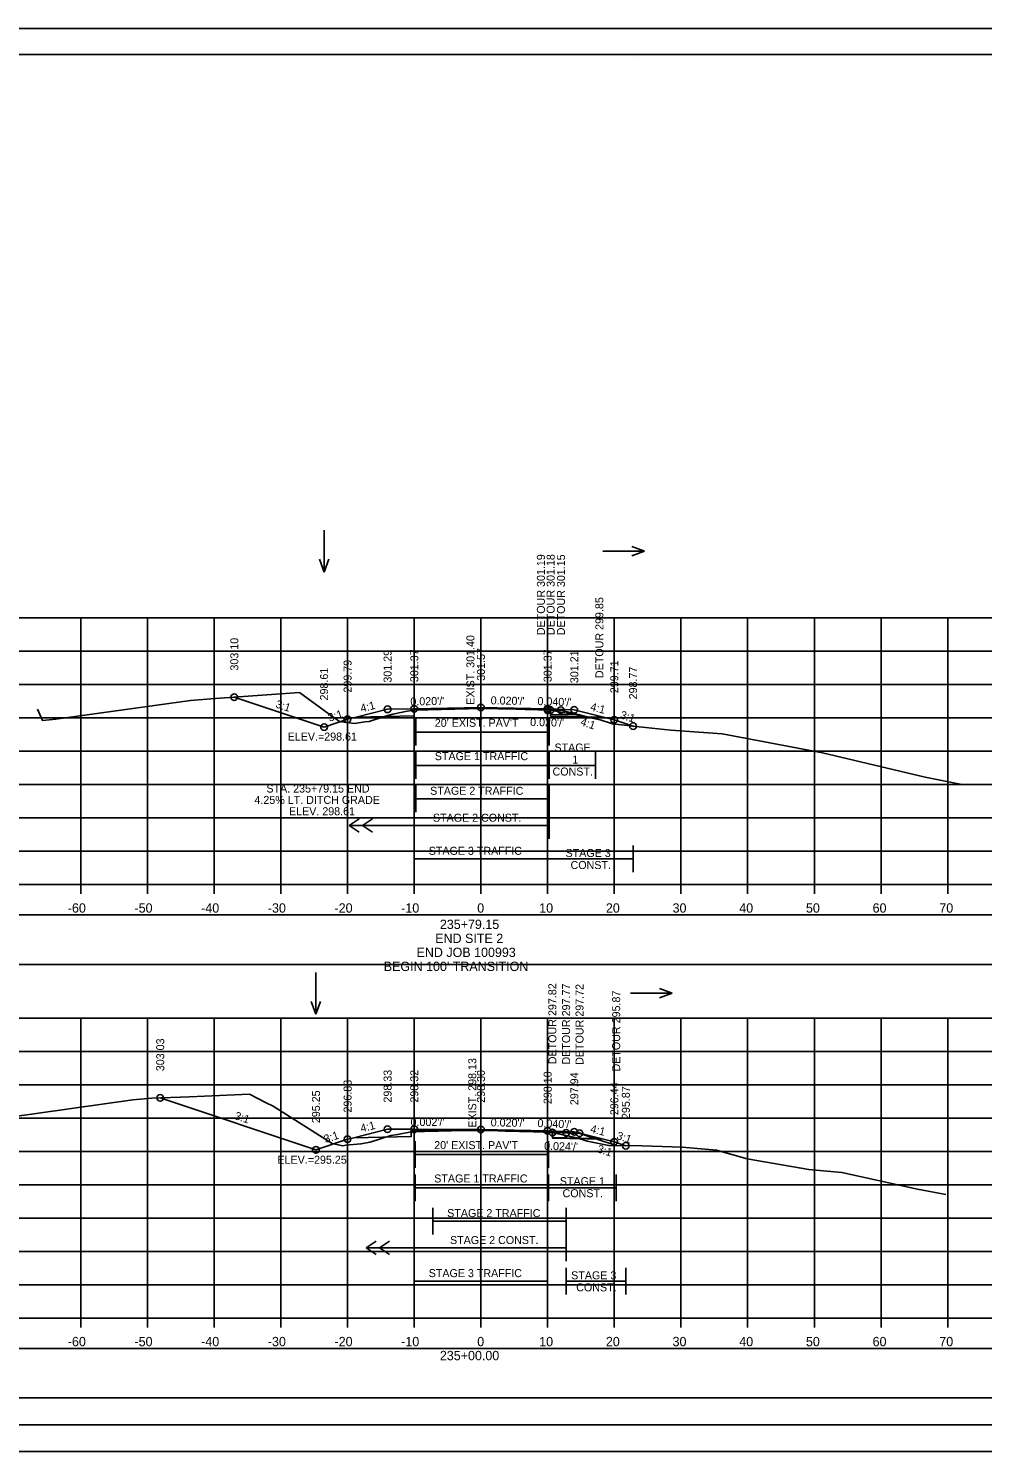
# Model space of a CAD drawing. Extents: x 4667 to 1632277, y -2100 to 724501.
# Drawn here: x 5709.3 to 5852.4, y 1449.6 to 1663 of the extents above; entities that cross this region are included whole.
import ezdxf

# ---------------------------------------------------------------- set-up
doc = ezdxf.new("R2010")
doc.units = 0
for name, color, linetype in [('R_Alt Surface', 7, 'Continuous'), ('R_Axis', 7, 'Continuous'), ('R_Axis Annot', 7, 'Continuous'), ('R_Border', 7, 'Continuous'), ('R_Detour', 7, 'Continuous'), ('R_Detour Annot', 7, 'Continuous'), ('R_Exist Surface', 7, 'Continuous'), ('R_Fin Surface', 7, 'Continuous'), ('R_Fin Surface Annot', 7, 'Continuous'), ('R_Grid', 7, 'Continuous'), ('R_No Plot', 7, 'Continuous'), ('R_Proposed CofA', 7, 'Continuous'), ('R_Temp Easement', 7, 'Continuous'), ('R_Water Annot', 7, 'Continuous'), ('T_Notes', 7, 'Continuous')]:
    doc.layers.add(name, color=color, linetype=linetype)

msp = doc.modelspace()

# ---------------------------------------------------------------- linework, layer by layer
at = {"layer": 'R_Alt Surface'}
for points in [[(5758.47, 1559.74), (5767.18, 1559.91), (5767.18, 1560.83), (5777.18, 1561.03), (5787.63, 1560.82), (5787.63, 1559.9), (5795.55, 1559.74)], [(5758.13, 1496.69), (5766.72, 1496.87), (5766.72, 1497.78), (5777.18, 1497.76), (5787.89, 1497.55), (5787.89, 1496.63), (5795.55, 1496.48)]]:
    msp.add_lwpolyline(points, dxfattribs=at)
at = {"layer": 'R_Axis'}
for p, q in [((5667.18, 1534.63), (5947.18, 1534.63)), ((5717.18, 1533.23), (5717.18, 1534.63)), ((5727.18, 1533.23), (5727.18, 1534.63)), ((5737.18, 1533.23), (5737.18, 1534.63)), ((5747.18, 1533.23), (5747.18, 1534.63)), ((5757.18, 1533.23), (5757.18, 1534.63)), ((5767.18, 1533.23), (5767.18, 1534.63)), ((5777.18, 1533.23), (5777.18, 1534.63)), ((5787.18, 1533.23), (5787.18, 1534.63)), ((5797.18, 1533.23), (5797.18, 1534.63)), ((5807.18, 1533.23), (5807.18, 1534.63)), ((5817.18, 1533.23), (5817.18, 1534.63)), ((5827.18, 1533.23), (5827.18, 1534.63)), ((5837.18, 1533.23), (5837.18, 1534.63)), ((5847.18, 1533.23), (5847.18, 1534.63)), ((5667.18, 1469.63), (5947.18, 1469.63)), ((5717.18, 1468.23), (5717.18, 1469.63)), ((5727.18, 1468.23), (5727.18, 1469.63)), ((5737.18, 1468.23), (5737.18, 1469.63)), ((5747.18, 1468.23), (5747.18, 1469.63)), ((5757.18, 1468.23), (5757.18, 1469.63)), ((5767.18, 1468.23), (5767.18, 1469.63)), ((5777.18, 1468.23), (5777.18, 1469.63)), ((5787.18, 1468.23), (5787.18, 1469.63)), ((5797.18, 1468.23), (5797.18, 1469.63)), ((5807.18, 1468.23), (5807.18, 1469.63)), ((5817.18, 1468.23), (5817.18, 1469.63)), ((5827.18, 1468.23), (5827.18, 1469.63)), ((5837.18, 1468.23), (5837.18, 1469.63)), ((5847.18, 1468.23), (5847.18, 1469.63))]:
    msp.add_line(p, q, dxfattribs=at)
at = {"layer": 'R_Border'}
for p, q in [((5648.18, 1659.09), (5964.36, 1659.09)), ((5800.7, 1658.83), (5800.7, 1658.83)), ((5800.7, 1658.83), (5800.7, 1658.83)), ((5964.36, 1453.63), (5648.18, 1453.63))]:
    msp.add_line(p, q, dxfattribs=at)
at = {"layer": 'R_Detour'}
for points in [[(5792.04, 1560.06), (5787.64, 1560.15), (5787.63, 1560.8)], [(5787.63, 1560.8), (5789.18, 1560.77), (5794.37, 1559.48)], [(5794.23, 1496.59), (5787.89, 1496.74), (5787.88, 1497.45)], [(5787.88, 1497.45), (5789.43, 1497.41), (5789.95, 1497.4), (5790.57, 1497.38), (5791.96, 1497.35), (5792.92, 1497.03), (5795.29, 1496.23), (5796.54, 1495.81), (5797.46, 1495.5)]]:
    msp.add_lwpolyline(points, dxfattribs=at)
at = {"layer": 'R_Exist Surface'}
for points in [[(5710.65, 1560.91), (5711.43, 1559.21), (5713.41, 1559.43), (5733.6, 1562.23), (5736.68, 1562.47), (5749.97, 1563.43), (5754.4, 1560.18), (5755.97, 1559.06), (5756.27, 1559.02), (5758.23, 1558.81), (5759.77, 1559.05), (5760.41, 1559.08), (5762.86, 1559.87), (5763.94, 1560.16), (5766.11, 1560.62), (5767.18, 1560.79), (5775.32, 1560.98), (5778.27, 1561.05), (5780.77, 1560.97), (5787.63, 1560.8), (5789.75, 1560.37), (5790.44, 1560.26), (5795.05, 1559.34), (5796.9, 1558.75), (5800.91, 1558.29), (5805.65, 1557.78), (5813.35, 1557.24), (5816.82, 1556.6), (5828.38, 1554.39), (5843.81, 1550.76), (5849.07, 1549.7)], [(5706.23, 1499.72), (5724.99, 1502.35), (5727.84, 1502.61), (5733.45, 1502.84), (5742.47, 1503.2), (5744.99, 1501.94), (5746.04, 1501.42), (5754.85, 1495.8), (5755.76, 1495.61), (5756.46, 1495.49), (5756.93, 1495.55), (5759.17, 1495.76), (5760.55, 1496.01), (5763.65, 1497.01), (5764.67, 1497.17), (5766.72, 1497.59), (5774.81, 1497.75), (5777.95, 1497.76), (5785.06, 1497.58), (5787.89, 1497.45), (5788.74, 1497.25), (5791.58, 1496.67), (5793.1, 1496.19), (5796.37, 1495.51), (5801.34, 1495.48), (5807.38, 1495.27), (5812.52, 1494.83), (5817.11, 1493.5), (5826.33, 1491.92), (5831.31, 1491.49), (5842.65, 1489), (5846.91, 1488.2)]]:
    msp.add_lwpolyline(points, dxfattribs=at)
at = {"layer": 'R_Fin Surface'}
for points in [[(5740.19, 1562.72), (5753.65, 1558.24), (5757.18, 1559.41), (5758.47, 1559.74), (5763.18, 1560.91), (5767.18, 1560.99), (5777.18, 1561.19), (5787.18, 1560.99), (5791.18, 1560.83), (5795.55, 1559.74), (5797.18, 1559.33), (5799.99, 1558.4)], [(5729.08, 1502.66), (5752.44, 1494.87), (5757.18, 1496.46), (5758.13, 1496.69), (5763.18, 1497.96), (5767.18, 1497.95), (5777.18, 1497.93), (5787.18, 1497.73), (5791.18, 1497.57), (5795.55, 1496.48), (5797.18, 1496.07), (5798.91, 1495.49)]]:
    msp.add_lwpolyline(points, dxfattribs=at)
at = {"layer": 'R_Grid'}
for p, q in [((5667.18, 1574.63), (5947.18, 1574.63)), ((5717.18, 1534.63), (5717.18, 1574.63)), ((5727.18, 1534.63), (5727.18, 1574.63)), ((5737.18, 1534.63), (5737.18, 1574.63)), ((5747.18, 1534.63), (5747.18, 1574.63)), ((5757.18, 1534.63), (5757.18, 1574.63)), ((5767.18, 1534.63), (5767.18, 1574.63)), ((5777.18, 1534.63), (5777.18, 1574.63)), ((5787.18, 1534.63), (5787.18, 1574.63)), ((5797.18, 1534.63), (5797.18, 1574.63)), ((5807.18, 1534.63), (5807.18, 1574.63)), ((5817.18, 1534.63), (5817.18, 1574.63)), ((5827.18, 1534.63), (5827.18, 1574.63)), ((5837.18, 1534.63), (5837.18, 1574.63)), ((5847.18, 1534.63), (5847.18, 1574.63)), ((5667.18, 1569.63), (5947.18, 1569.63)), ((5667.18, 1564.63), (5947.18, 1564.63)), ((5667.18, 1559.63), (5947.18, 1559.63)), ((5667.18, 1554.63), (5947.18, 1554.63)), ((5667.18, 1549.63), (5947.18, 1549.63)), ((5667.18, 1544.63), (5947.18, 1544.63)), ((5667.18, 1539.63), (5947.18, 1539.63)), ((5667.18, 1534.63), (5947.18, 1534.63)), ((5667.18, 1514.63), (5947.18, 1514.63)), ((5717.18, 1469.63), (5717.18, 1514.63)), ((5727.18, 1469.63), (5727.18, 1514.63)), ((5737.18, 1469.63), (5737.18, 1514.63)), ((5747.18, 1469.63), (5747.18, 1514.63)), ((5757.18, 1469.63), (5757.18, 1514.63)), ((5767.18, 1469.63), (5767.18, 1514.63)), ((5777.18, 1469.63), (5777.18, 1514.63)), ((5787.18, 1469.63), (5787.18, 1514.63)), ((5797.18, 1469.63), (5797.18, 1514.63)), ((5807.18, 1469.63), (5807.18, 1514.63)), ((5817.18, 1469.63), (5817.18, 1514.63)), ((5827.18, 1469.63), (5827.18, 1514.63)), ((5837.18, 1469.63), (5837.18, 1514.63)), ((5847.18, 1469.63), (5847.18, 1514.63)), ((5667.18, 1509.63), (5947.18, 1509.63)), ((5667.18, 1504.63), (5947.18, 1504.63)), ((5667.18, 1499.63), (5947.18, 1499.63)), ((5667.18, 1494.63), (5947.18, 1494.63)), ((5667.18, 1489.63), (5947.18, 1489.63)), ((5667.18, 1484.63), (5947.18, 1484.63)), ((5667.18, 1479.63), (5947.18, 1479.63)), ((5667.18, 1474.63), (5947.18, 1474.63)), ((5667.18, 1469.63), (5947.18, 1469.63))]:
    msp.add_line(p, q, dxfattribs=at)
at = {"layer": 'R_No Plot'}
for p, q in [((5635.78, 1662.98), (5969.12, 1662.98)), ((5635.78, 1449.65), (5969.12, 1449.65))]:
    msp.add_line(p, q, dxfattribs=at)
for points in [[(5635.78, 1662.98), (5969.12, 1662.98), (5969.12, 1449.64), (5635.78, 1449.64)], [(5882.1, 1659.09), (5901.72, 1659.09), (5901.72, 1649.21), (5917.84, 1649.21), (5941.04, 1649.21), (5941.04, 1624.87), (5964.36, 1624.87), (5964.36, 1453.63), (5648.18, 1453.63), (5648.18, 1659.09)]]:
    msp.add_lwpolyline(points, close=True, dxfattribs=at)
for centre in [(5740.19, 1562.72), (5777.18, 1561.19), (5757.18, 1559.41), (5763.18, 1560.91), (5767.18, 1560.99), (5787.18, 1560.99), (5787.18, 1560.81), (5787.63, 1560.8), (5789.18, 1560.77), (5791.18, 1560.83), (5797.18, 1559.33), (5753.65, 1558.24), (5799.99, 1558.4), (5729.08, 1502.66), (5763.18, 1497.96), (5767.18, 1497.95), (5777.18, 1497.93), (5787.18, 1497.73), (5787.89, 1497.45), (5789.95, 1497.4), (5791.18, 1497.57), (5791.96, 1497.35), (5757.18, 1496.46), (5797.18, 1496.07), (5798.91, 1495.49), (5752.44, 1494.87)]:
    msp.add_circle(centre, 0.5, dxfattribs=at)
at = {"layer": 'R_Proposed CofA'}
for p, q in [((5757.4, 1543.49), (5758.9, 1544.49)), ((5757.4, 1543.49), (5758.9, 1542.49)), ((5759.4, 1543.49), (5760.9, 1544.49)), ((5759.4, 1543.49), (5760.9, 1542.49)), ((5759.95, 1480.18), (5761.45, 1481.18)), ((5761.95, 1480.18), (5763.45, 1481.18)), ((5759.95, 1480.18), (5761.45, 1479.18)), ((5761.95, 1480.18), (5763.45, 1479.18))]:
    msp.add_line(p, q, dxfattribs=at)
for points in [[(5667.23, 1522.68), (5947.13, 1522.68), (5947.13, 1530.1), (5667.23, 1530.1)], [(5667.23, 1457.68), (5947.13, 1457.68), (5947.13, 1465.1), (5667.23, 1465.1)]]:
    msp.add_lwpolyline(points, close=True, dxfattribs=at)
at = {"layer": 'R_Temp Easement'}
for p, q in [((5767.4, 1555.49), (5767.4, 1559.49)), ((5767.4, 1557.49), (5787.4, 1557.49)), ((5787.4, 1555.49), (5787.4, 1559.49)), ((5767.4, 1550.49), (5767.4, 1554.49)), ((5787.4, 1550.49), (5787.4, 1554.49)), ((5794.37, 1550.49), (5794.37, 1554.49)), ((5767.4, 1552.49), (5787.4, 1552.49)), ((5794.37, 1552.49), (5787.4, 1552.49)), ((5767.4, 1545.49), (5767.4, 1549.49)), ((5787.4, 1545.49), (5787.4, 1549.49)), ((5787.4, 1547.49), (5767.4, 1547.49)), ((5787.4, 1541.49), (5787.4, 1545.49)), ((5787.4, 1543.49), (5757.4, 1543.49)), ((5767.18, 1536.49), (5767.18, 1540.49)), ((5787.18, 1536.49), (5787.18, 1540.49)), ((5799.99, 1536.49), (5799.99, 1540.49)), ((5787.18, 1538.49), (5767.18, 1538.49)), ((5787.18, 1538.49), (5799.99, 1538.49)), ((5767.3, 1492.18), (5767.3, 1496.18)), ((5787.3, 1492.18), (5787.3, 1496.18)), ((5767.3, 1494.18), (5787.3, 1494.18)), ((5767.3, 1487.18), (5767.3, 1491.18)), ((5767.3, 1489.18), (5787.3, 1489.18)), ((5787.3, 1487.18), (5787.3, 1491.18)), ((5797.46, 1489.18), (5787.3, 1489.18)), ((5797.46, 1487.18), (5797.46, 1491.18)), ((5769.95, 1482.18), (5769.95, 1486.18)), ((5789.95, 1482.18), (5789.95, 1486.18)), ((5789.95, 1484.18), (5769.95, 1484.18)), ((5789.95, 1478.18), (5789.95, 1482.18)), ((5789.95, 1480.18), (5759.95, 1480.18)), ((5767.18, 1473.18), (5767.18, 1477.18)), ((5787.18, 1473.18), (5787.18, 1477.18)), ((5789.95, 1473.18), (5789.95, 1477.18)), ((5798.91, 1473.18), (5798.91, 1477.18)), ((5787.18, 1475.18), (5767.18, 1475.18)), ((5789.95, 1475.18), (5798.91, 1475.18))]:
    msp.add_line(p, q, dxfattribs=at)
at = {"layer": 'R_Water Annot'}
for p, q in [((5753.65, 1587.77), (5753.65, 1581.48)), ((5801.73, 1584.63), (5799.81, 1585.33)), ((5753.65, 1581.48), (5752.95, 1583.41)), ((5753.65, 1581.48), (5754.35, 1583.41)), ((5795.44, 1584.63), (5801.73, 1584.63)), ((5801.73, 1584.63), (5799.81, 1583.93)), ((5752.44, 1521.48), (5752.44, 1515.2)), ((5805.87, 1518.34), (5803.95, 1519.04)), ((5752.44, 1515.2), (5751.74, 1517.12)), ((5752.44, 1515.2), (5753.14, 1517.12)), ((5799.59, 1518.34), (5805.87, 1518.34)), ((5805.87, 1518.34), (5803.95, 1517.64))]:
    msp.add_line(p, q, dxfattribs=at)
at = {"layer": 'T_Notes'}
for p, q in [((5789.18, 1560.79), (5789.2, 1560.77)), ((5791.96, 1497.46), (5792.13, 1497.29))]:
    msp.add_line(p, q, dxfattribs=at)
for points in [[(5767.18, 1560.83), (5767.18, 1560.79), (5775.32, 1560.98), (5777.16, 1561.03)], [(5766.72, 1497.78), (5777.17, 1497.76), (5774.81, 1497.75), (5766.72, 1497.59)]]:
    msp.add_lwpolyline(points, close=True, dxfattribs=at)
for points in [[(5783.8, 1560.89), (5787.63, 1560.82), (5789.18, 1560.79)], [(5783.8, 1560.89), (5787.63, 1560.8), (5789.18, 1560.77), (5789.2, 1560.77)], [(5780.81, 1497.69), (5787.89, 1497.55), (5791.96, 1497.46)], [(5780.81, 1497.69), (5785.06, 1497.58), (5787.89, 1497.45), (5791.96, 1497.35), (5792.13, 1497.29)]]:
    msp.add_lwpolyline(points, dxfattribs=at)

# ---------------------------------------------------------------- texts
at = {"layer": 'R_Axis Annot'}
for s, p in [('-60', (5715.22, 1530.43)), ('-50', (5725.22, 1530.43)), ('-40', (5735.22, 1530.43)), ('-30', (5745.22, 1530.43)), ('-20', (5755.22, 1530.43)), ('-10', (5765.22, 1530.43)), ('0', (5776.62, 1530.43)), ('10', (5785.92, 1530.43)), ('20', (5795.92, 1530.43)), ('30', (5805.92, 1530.43)), ('40', (5815.92, 1530.43)), ('50', (5825.92, 1530.43)), ('60', (5835.92, 1530.43)), ('70', (5845.92, 1530.43)), ('235+79.15', (5771.02, 1527.98)), ('END SITE 2', (5770.32, 1525.88)), ('END JOB 100993', (5767.52, 1523.78)), ("BEGIN 100' TRANSITION", (5762.6, 1521.68)), ('-60', (5715.22, 1465.43)), ('-50', (5725.22, 1465.43)), ('-40', (5735.22, 1465.43)), ('-30', (5745.22, 1465.43)), ('-20', (5755.22, 1465.43)), ('-10', (5765.22, 1465.43)), ('0', (5776.62, 1465.43)), ('10', (5785.92, 1465.43)), ('20', (5795.92, 1465.43)), ('30', (5805.92, 1465.43)), ('40', (5815.92, 1465.43)), ('50', (5825.92, 1465.43)), ('60', (5835.92, 1465.43)), ('70', (5845.92, 1465.43)), ('235+00.00', (5771.02, 1463.33))]:
    msp.add_text(s, height=1.4, dxfattribs=at).set_placement(p)
at = {"layer": 'R_Detour Annot'}
for s, rotation, p in [('DETOUR 299.85', 90, (5795.54, 1565.59)), ("0.020'/'", 358.8542, (5784.55, 1558.41)), ('4:1', 341.5651, (5792, 1558.57)), ("0.024'/'", 358.6513, (5786.64, 1494.87)), ('3:1', 341.5651, (5794.51, 1494.54))]:
    msp.add_text(s, height=1.2, rotation=rotation, dxfattribs=at).set_placement(p)
at = {"layer": 'R_Fin Surface Annot'}
for s, rotation, p in [('DETOUR 301.19', 90, (5786.77, 1572.03)), ('DETOUR 301.18', 90, (5788.23, 1572.04)), ('DETOUR 301.15', 90, (5789.78, 1572.01)), ('303.10', 90, (5740.79, 1566.72)), ('299.79', 90, (5757.78, 1563.41)), ('301.29', 90, (5763.78, 1564.91)), ('301.37', 90, (5767.78, 1564.99)), ('301.57', 90, (5777.78, 1565.19)), ('301.37', 90, (5787.78, 1564.99)), ('301.21', 90, (5791.78, 1564.83)), ('299.71', 90, (5797.78, 1563.33)), ('298.61', 90, (5754.25, 1562.24)), ('298.77', 90, (5800.59, 1562.4)), ('3:1', 341.5651, (5746.29, 1561.22)), ('4:1', 14.0362, (5759.26, 1560.45)), ("0.020'/'", 1.1458, (5766.61, 1561.48)), ("0.020'/'", 358.8542, (5778.63, 1561.66)), ("0.040'/'", 357.7094, (5785.64, 1561.56)), ('4:1', 345.9638, (5793.5, 1560.77)), ('3:1', 18.4349, (5754.47, 1559.04)), ('3:1', 341.5651, (5797.96, 1559.6)), ('DETOUR 297.82', 90, (5788.49, 1507.71)), ('DETOUR 297.77', 90, (5790.55, 1507.66)), ('DETOUR 297.72', 90, (5792.56, 1507.61)), ('DETOUR 295.87', 90, (5798.06, 1506.61)), ('303.03', 90, (5729.68, 1506.66)), ('298.33', 90, (5763.78, 1501.96)), ('298.32', 90, (5767.78, 1501.95)), ('298.30', 90, (5777.78, 1501.93)), ('298.10', 90, (5787.78, 1501.73)), ('297.94', 90, (5791.78, 1501.57)), ('296.83', 90, (5757.78, 1500.46)), ('296.44', 90, (5797.78, 1500.07)), ('295.87', 90, (5799.51, 1499.49)), ('295.25', 90, (5753.04, 1498.87)), ('3:1', 341.5651, (5740.13, 1499.5)), ('4:1', 14.0362, (5759.26, 1497.49)), ("0.002'/'", 359.8762, (5766.62, 1498.45)), ("0.020'/'", 358.8542, (5778.63, 1498.4)), ("0.040'/'", 357.7094, (5785.64, 1498.29)), ('4:1', 345.9638, (5793.5, 1497.5)), ('3:1', 18.4349, (5753.86, 1495.88)), ('3:1', 341.5651, (5797.42, 1496.52))]:
    msp.add_text(s, height=1.2, rotation=rotation, dxfattribs=at).set_placement(p)
at = {"layer": 'R_Temp Easement'}
for s, p in [('EXIST. 301.40', (5776.2, 1561.6)), ('EXIST. 298.13', (5776.48, 1498.19))]:
    msp.add_text(s, height=1.2, rotation=90, dxfattribs=at).set_placement(p)
for s, height, p in [("20' EXIST. PAV'T", 1.2, (5770.26, 1558.29)), ('STAGE', 1.199, (5788.21, 1554.58)), ('STAGE 1 TRAFFIC', 1.2, (5770.26, 1553.29)), ('1', 1.2, (5790.89, 1552.78)), ('CONST.', 1.199, (5787.92, 1550.98)), ('STAGE 2 TRAFFIC', 1.1985, (5769.56, 1548.1)), ('STAGE 2 CONST.', 1.1985, (5769.98, 1544.06)), ('STAGE 3 TRAFFIC', 1.1985, (5769.35, 1539.1)), ('STAGE 3', 1.199, (5789.87, 1538.77)), ('CONST.', 1.199, (5790.62, 1536.97)), ("20' EXIST. PAV'T", 1.2, (5770.17, 1494.98)), ('STAGE 1 TRAFFIC', 1.2, (5770.17, 1489.98)), ('STAGE 1', 1.199, (5789.01, 1489.57)), ('CONST.', 1.199, (5789.42, 1487.77)), ('STAGE 2 TRAFFIC', 1.1985, (5772.12, 1484.79)), ('STAGE 2 CONST.', 1.1985, (5772.54, 1480.75)), ('STAGE 3 TRAFFIC', 1.1985, (5769.35, 1475.79)), ('STAGE 3', 1.199, (5790.71, 1475.46)), ('CONST.', 1.199, (5791.47, 1473.66))]:
    msp.add_text(s, height=height, dxfattribs=at).set_placement(p)
at = {"layer": 'R_Water Annot'}
for s, p in [('ELEV.=298.61', (5748.19, 1556.23)), ('STA. 235+79.15 END', (5745, 1548.43)), ('4.25% LT. DITCH GRADE', (5743.21, 1546.73)), ('ELEV. 298.61', (5748.39, 1545.03)), ('ELEV.=295.25', (5746.66, 1492.79))]:
    msp.add_text(s, height=1.2, dxfattribs=at).set_placement(p)

doc.saveas('drawing.dxf')
